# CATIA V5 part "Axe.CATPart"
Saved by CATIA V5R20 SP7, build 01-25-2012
Part number: Axe
Publications: "Corps principal", "Face"
Bounding box of the stored display mesh (mm): x 1.51 to 6.31, y -86.545 to -53.808, z -11.126 to 38.408
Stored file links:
  F:\Travaux\Modélisations\CFAO_2011\MMS\MMS_GR2\AA_OK\jboiteux\Catia\Axe.CATPart
  U:\finthinkmotion\stepper.CATProduct
  F:\Travaux\Modélisations\CFAO_2011\MMS\MMS_GR2\AA_OK\jboiteux\Catia\Part2.CATPart
  F:\Travaux\Modélisations\CFAO_2011\MMS\MMS_GR2\AA_OK\jboiteux\Catia\Roulement plastique.CATPart
  F:\Travaux\Modélisations\CFAO_2011\MMS\MMS_GR2\AA_OK\jboiteux\Catia\bati.CATPart
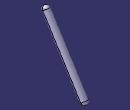
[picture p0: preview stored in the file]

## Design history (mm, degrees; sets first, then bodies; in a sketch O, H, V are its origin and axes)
Parameters
  `rayon roulement` = 9 mm {= External.royontubebati}
External parameters (linked from other documents)
  External.royontubebati = 9 mm
Set1
  Plane1: linked copy from another document
  DatumCurve1: linked copy from another document
Body1 (main body)
  Sketch1 on Plane1, origin (0, -25.8368, 41.3475), H (1, 0, 0), V (0, 0.848, 0.5299)
    projected circle E1 centre (3.91, -52.2845) radius 2.4 from edge of DatumCurve1
  Pad1: profile Sketch1, direction (0, 0.5299, -0.848), length 28.8 {= `rayon roulement` *3.2}, mirrored extent
  Fillet1: radius 2.3 {= `rayon roulement` /9*2.3}, on edge [end face of Pad1 | face of Pad1 from Sketch1.E1]; edge [face of Pad1 from Sketch1.E1 | start face of Pad1]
